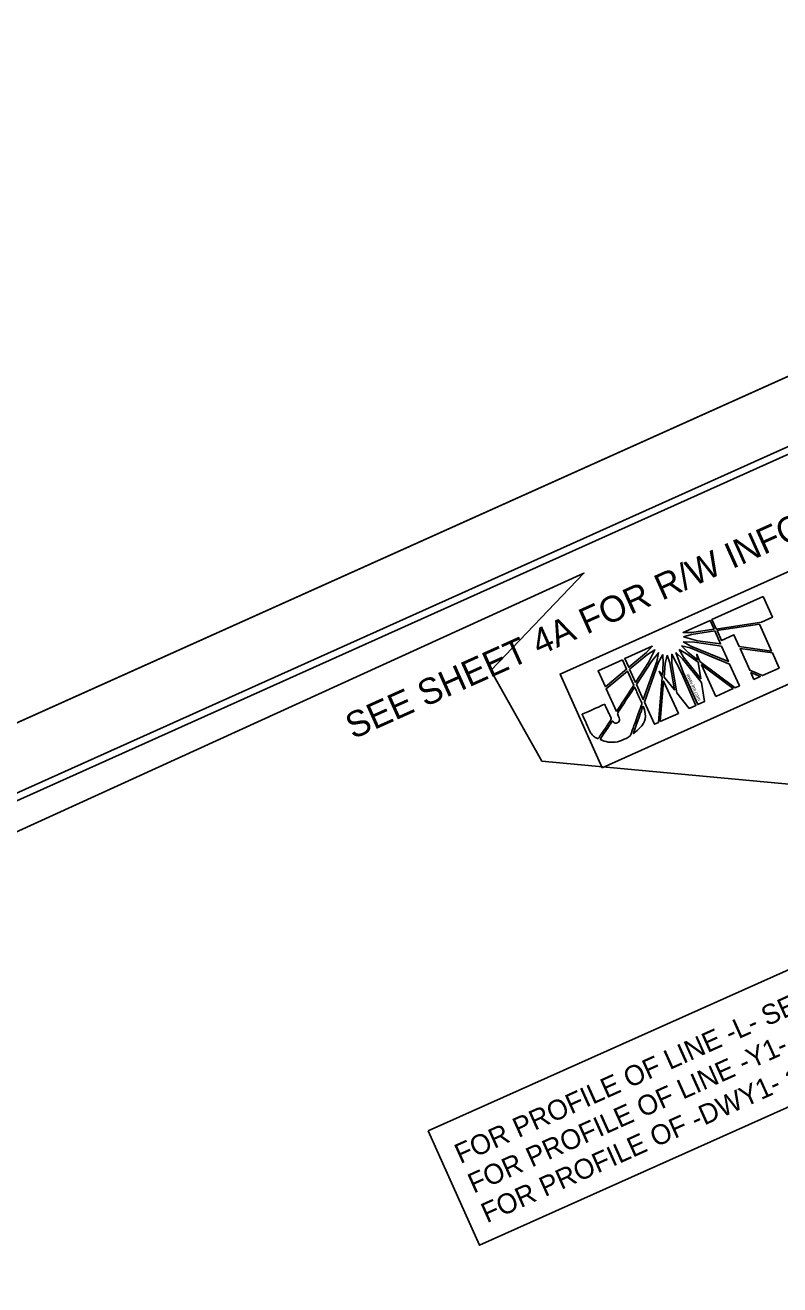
# Model space of a CAD drawing. Extents: x 553939 to 555925, y 502653 to 504347.
# Drawn here: x 554932.1 to 555197.2, y 503904.2 to 504346.6 of the extents above; entities that cross this region are included whole.
import ezdxf

# ---------------------------------------------------------------- set-up
doc = ezdxf.new("R2010")
doc.units = 0
for name, color, linetype in [('Matchline', 7, 'Continuous'), ('Prop Horizontal Alignment Curve and Spiral Data', 7, 'Continuous'), ('Sheet Border Standard 30in CELL', 7, 'Continuous'), ('Sheet Clip Boundary CELL', 7, 'Continuous'), ('Sheet Cutting Line CELL', 7, 'Continuous'), ('Sheet Plot Border Inside CELL', 7, 'Continuous'), ('Sheet Plot Border Outside CELL', 7, 'Continuous')]:
    doc.layers.add(name, color=color, linetype=linetype)

msp = doc.modelspace()

# ---------------------------------------------------------------- linework, layer by layer
at = {"layer": 'Matchline'}
for p, q in [((555191.33, 504145.99), (555173.38, 504137.91)), ((555194.64, 504138.64), (555191.33, 504145.99)), ((555172.74, 504137.57), (555163.26, 504133.36)), ((555174.12, 504134.5), (555172.74, 504137.57)), ((555173.38, 504137.91), (555174.87, 504134.62)), ((555190.82, 504136.92), (555194.64, 504138.64)), ((555163.26, 504133.36), (555166.16, 504133.31)), ((555166.16, 504133.31), (555174.12, 504134.5)), ((555174.41, 504133.86), (555166.2, 504132.58)), ((555176.39, 504129.31), (555174.41, 504133.86)), ((555174.87, 504134.62), (555174.91, 504134.52)), ((555174.91, 504134.52), (555190.82, 504136.92)), ((555190.07, 504136.19), (555175.14, 504134.01)), ((555175.14, 504134.01), (555175.17, 504133.96)), ((555175.17, 504133.96), (555176.71, 504130.52)), ((555194.31, 504126.77), (555190.07, 504136.19)), ((555152.38, 504128.46), (555142.77, 504124.14)), ((555150.42, 504126.27), (555152.38, 504128.46)), ((555162.72, 504128.59), (555165, 504126.33)), ((555165.78, 504127.87), (555162.72, 504128.59)), ((555163.26, 504130.07), (555165.97, 504128.46)), ((555167.3, 504129.91), (555163.26, 504130.07)), ((555166.2, 504132.58), (555163.41, 504131.73)), ((555163.41, 504131.73), (555168.31, 504130.41)), ((555165.97, 504128.46), (555179.2, 504123.08)), ((555176.74, 504128.55), (555167.3, 504129.91)), ((555168.31, 504130.41), (555176.39, 504129.31)), ((555176.71, 504130.52), (555181.09, 504132.49)), ((555179.2, 504123.08), (555176.74, 504128.55)), ((555181.09, 504132.49), (555182.94, 504128.39)), ((555182.94, 504128.39), (555194.31, 504126.77)), ((555142.77, 504124.14), (555144.15, 504121.08)), ((555144.15, 504121.08), (555150.42, 504126.27)), ((555150.72, 504125.61), (555144.45, 504120.42)), ((555153.35, 504127.2), (555150.72, 504125.61)), ((555151.11, 504122.74), (555153.35, 504127.2)), ((555154.65, 504126.2), (555152.14, 504123.08)), ((555154.05, 504123.14), (555154.65, 504126.2)), ((555156.1, 504125.61), (555154.62, 504122.84)), ((555156.29, 504122.41), (555156.1, 504125.61)), ((555157.67, 504125.4), (555156.96, 504122.47)), ((555158.62, 504122.66), (555157.67, 504125.4)), ((555162.65, 504119.09), (555159.25, 504125.66)), ((555159.25, 504125.66), (555159.31, 504122.4)), ((555160.66, 504126.29), (555163.25, 504119.36)), ((555163.02, 504124.07), (555160.66, 504126.29)), ((555161.85, 504127.29), (555163.37, 504124.68)), ((555164.48, 504125.86), (555161.85, 504127.29)), ((555169.68, 504115.8), (555163.02, 504124.07)), ((555163.37, 504124.68), (555169.46, 504117.06)), ((555168.49, 504122.85), (555164.48, 504125.86)), ((555165, 504126.33), (555168.36, 504123.76)), ((555179.6, 504122.2), (555165.78, 504127.87)), ((555168.36, 504123.76), (555168.03, 504125.65)), ((555168.03, 504125.65), (555169.15, 504123.15)), ((555183.26, 504127.69), (555186.69, 504120.05)), ((555194.61, 504126.11), (555183.26, 504127.69)), ((555196.99, 504120.81), (555194.61, 504126.11)), ((555141.91, 504123.69), (555133.37, 504119.85)), ((555133.37, 504119.85), (555135.92, 504114.19)), ((555135.92, 504114.19), (555143.39, 504120.4)), ((555143.67, 504119.78), (555136.21, 504113.54)), ((555143.39, 504120.4), (555141.91, 504123.69)), ((555145.89, 504114.83), (555143.67, 504119.78)), ((555144.45, 504120.42), (555146.53, 504115.8)), ((555146.53, 504115.8), (555151.11, 504122.74)), ((555152.14, 504123.08), (555146.86, 504115.05)), ((555149.26, 504109.73), (555154.05, 504123.14)), ((555154.62, 504122.84), (555149.67, 504108.82)), ((555155.86, 504117.46), (555154.85, 504119.71)), ((555154.85, 504119.71), (555155.97, 504118.35)), ((555155.97, 504118.35), (555156.29, 504122.41)), ((555156.96, 504122.47), (555156.57, 504117.66)), ((555160.24, 504113.14), (555158.62, 504122.66)), ((555159.31, 504122.4), (555161.06, 504112.09)), ((555169.46, 504117.06), (555168.49, 504122.85)), ((555169.15, 504123.15), (555181.54, 504113.85)), ((555180.82, 504113.58), (555169.71, 504121.93)), ((555169.71, 504121.93), (555174.7, 504110.83)), ((555183.05, 504114.53), (555179.6, 504122.2)), ((555186.69, 504120.05), (555191.2, 504118.2)), ((555191.2, 504118.2), (555196.99, 504120.81)), ((555154.56, 504101.71), (555155.86, 504117.46)), ((555156.41, 504116.23), (555155.23, 504102.01)), ((555161.59, 504104.87), (555156.41, 504116.23)), ((555156.57, 504117.66), (555160.24, 504113.14)), ((555167.77, 504107.71), (555162.65, 504119.09)), ((555163.25, 504119.36), (555168.38, 504107.98)), ((555170.74, 504109.05), (555169.68, 504115.8)), ((555190.36, 504117.82), (555187.07, 504119.22)), ((555187.07, 504119.22), (555188.14, 504116.83)), ((555188.14, 504116.83), (555190.36, 504117.82)), ((555136.21, 504113.54), (555139.79, 504105.58)), ((555139.79, 504105.58), (555145.89, 504114.83)), ((555146.86, 504115.05), (555149.26, 504109.73)), ((555161.06, 504112.09), (555165.43, 504106.65)), ((555174.7, 504110.83), (555180.82, 504113.58)), ((555181.54, 504113.85), (555183.05, 504114.53)), ((555149.67, 504108.82), (555153.16, 504101.08)), ((555165.43, 504106.65), (555167.77, 504107.71)), ((555168.38, 504107.98), (555170.74, 504109.05)), ((555155.23, 504102.01), (555161.59, 504104.87)), ((555153.16, 504101.08), (555154.56, 504101.71))]:
    msp.add_line(p, q, dxfattribs=at)
msp.add_lwpolyline([(555134.79, 504085.77), (555317.28, 504167.72), (555302.49, 504200.65), (555120.01, 504118.71)], close=True, dxfattribs=at)
for points in [[(555191.33, 504145.99), (555173.38, 504137.91), (555174.87, 504134.62), (555174.91, 504134.52), (555190.82, 504136.92), (555194.64, 504138.64), (555191.33, 504145.99)], [(555166.16, 504133.31), (555174.12, 504134.5), (555172.74, 504137.57), (555163.26, 504133.36), (555166.16, 504133.31)], [(555163.41, 504131.73), (555168.31, 504130.41), (555176.39, 504129.31), (555174.41, 504133.86), (555166.2, 504132.58), (555163.41, 504131.73)], [(555175.14, 504134.01), (555175.17, 504133.96), (555176.71, 504130.52), (555181.09, 504132.49), (555182.94, 504128.39), (555194.31, 504126.77), (555190.07, 504136.19), (555175.14, 504134.01)], [(555150.42, 504126.27), (555152.38, 504128.46), (555142.77, 504124.14), (555144.15, 504121.08), (555150.42, 504126.27)], [(555162.72, 504128.59), (555165, 504126.33), (555168.36, 504123.76), (555168.03, 504125.65), (555169.15, 504123.15), (555181.54, 504113.85), (555183.05, 504114.53), (555179.6, 504122.2), (555165.78, 504127.87), (555162.72, 504128.59)], [(555163.26, 504130.07), (555165.97, 504128.46), (555179.2, 504123.08), (555176.74, 504128.55), (555167.3, 504129.91), (555163.26, 504130.07)], [(555144.45, 504120.42), (555146.53, 504115.8), (555151.11, 504122.74), (555153.35, 504127.2), (555150.72, 504125.61), (555144.45, 504120.42)], [(555146.86, 504115.05), (555149.26, 504109.73), (555154.05, 504123.14), (555154.65, 504126.2), (555152.14, 504123.08), (555146.86, 504115.05)], [(555156.1, 504125.61), (555154.62, 504122.84), (555149.67, 504108.82), (555153.16, 504101.08), (555154.56, 504101.71), (555155.86, 504117.46), (555154.85, 504119.71), (555155.97, 504118.35), (555156.29, 504122.41), (555156.1, 504125.61)], [(555157.67, 504125.4), (555156.96, 504122.47), (555156.57, 504117.66), (555160.24, 504113.14), (555158.62, 504122.66), (555157.67, 504125.4)], [(555159.31, 504122.4), (555161.06, 504112.09), (555165.43, 504106.65), (555167.77, 504107.71), (555162.65, 504119.09), (555159.25, 504125.66), (555159.31, 504122.4)], [(555160.66, 504126.29), (555163.25, 504119.36), (555168.38, 504107.98), (555170.74, 504109.05), (555169.68, 504115.8), (555163.02, 504124.07), (555160.66, 504126.29)], [(555161.85, 504127.29), (555163.37, 504124.68), (555169.46, 504117.06), (555168.49, 504122.85), (555164.48, 504125.86), (555161.85, 504127.29)], [(555183.26, 504127.69), (555186.69, 504120.05), (555191.2, 504118.2), (555196.99, 504120.81), (555194.61, 504126.11), (555183.26, 504127.69), (555183.26, 504127.69)], [(555135.92, 504114.19), (555143.39, 504120.4), (555141.91, 504123.69), (555133.37, 504119.85), (555135.92, 504114.19)], [(555139.79, 504105.58), (555145.89, 504114.83), (555143.67, 504119.78), (555136.21, 504113.54), (555139.79, 504105.58)], [(555174.7, 504110.83), (555180.82, 504113.58), (555169.71, 504121.93), (555174.7, 504110.83)], [(555155.23, 504102.01), (555161.59, 504104.87), (555156.41, 504116.23), (555155.23, 504102.01)], [(555188.14, 504116.83), (555188.14, 504116.83), (555190.36, 504117.82), (555187.07, 504119.22), (555188.14, 504116.83)]]:
    msp.add_lwpolyline(points, dxfattribs=at)
for points in [[(555140.12, 504101.58), (555139.61, 504101.35), (555139.05, 504101.44), (555138.44, 504102.3), (555138.44, 504102.3), (555134.02, 504095.75), (555134.02, 504095.75), (555136.8, 504094.61), (555140.35, 504094.79), (555142.9, 504095.93), (555143.56, 504096.23), (555144.04, 504096.52), (555144.68, 504096.97), (555144.68, 504096.97), (555148.8, 504108.38), (555148.8, 504108.38), (555148.8, 504108.38), (555146.21, 504114.13), (555146.21, 504114.13), (555146.21, 504114.13), (555140.12, 504104.86), (555140.12, 504104.86), (555141.09, 504102.71), (555140.83, 504101.9), (555140.12, 504101.58)], [(555140.12, 504101.58), (555139.61, 504101.35), (555139.05, 504101.44), (555138.44, 504102.3), (555138.44, 504102.3), (555134.02, 504095.75), (555134.02, 504095.75), (555136.8, 504094.61), (555140.35, 504094.79), (555142.9, 504095.93), (555143.56, 504096.23), (555144.04, 504096.52), (555144.68, 504096.97), (555144.68, 504096.97), (555148.8, 504108.38), (555148.8, 504108.38), (555148.8, 504108.38), (555146.21, 504114.13), (555146.21, 504114.13), (555146.21, 504114.13), (555140.12, 504104.86), (555140.12, 504104.86), (555141.09, 504102.71), (555140.83, 504101.9), (555140.12, 504101.58)], [(555135.69, 504108.14), (555135.69, 504108.14), (555127.79, 504104.58), (555127.79, 504104.58), (555127.79, 504104.58), (555130.02, 504099.64), (555130.02, 504099.64), (555130.02, 504099.64), (555130.25, 504099.12), (555130.25, 504099.12), (555130.95, 504097.57), (555132.01, 504096.57), (555133.37, 504095.95), (555133.37, 504095.95), (555138.09, 504102.82), (555138.05, 504102.91), (555138.05, 504102.91), (555135.69, 504108.14), (555135.69, 504108.14)], [(555149.2, 504107.48), (555149.2, 504107.48), (555145.64, 504097.63), (555145.64, 504097.63), (555148.54, 504099.9), (555150.81, 504103.51), (555149.2, 504107.48)]]:
    msp.add_open_spline(points, degree=3, dxfattribs=at)
at = {"layer": 'Prop Horizontal Alignment Curve and Spiral Data'}
msp.add_lwpolyline([(555073.67, 503958.23), (555091.71, 503918.08), (555365.32, 504040.41), (555347.29, 504080.56), (555073.67, 503958.23)], dxfattribs=at)
at = {"layer": 'Sheet Border Standard 30in CELL'}
msp.add_lwpolyline([(555469.6, 504316.85), (554101.23, 503702.4), (554531.34, 502744.54), (555899.72, 503358.98)], close=True, dxfattribs=at)
at = {"layer": 'Sheet Clip Boundary CELL'}
for points in [[(554122.43, 503695.68), (555128.42, 504154.2), (555095.7, 504120), (555113.65, 504088.12), (555364.03, 504064.84), (555538.05, 504147.98), (555542.54, 504077.37), (555561.42, 504000.98), (555608.35, 503927.62), (555814.87, 503478.7), (555868.57, 503357.36), (555699.98, 503280.3), (555640.99, 503255.83), (555512.69, 503541.56), (555029.44, 503324.56), (555157.75, 503038.83), (555094.66, 503015.3), (554759.27, 502917.8)], [(554122.43, 503695.68), (555128.42, 504154.2), (555095.7, 504120), (555113.65, 504088.12), (555364.03, 504064.84), (555538.05, 504147.98), (555542.54, 504077.37), (555561.42, 504000.98), (555610.11, 503951.13), (555644.95, 503906.87), (555662.42, 503867.97), (555642.54, 503853.07), (555814.87, 503478.7), (555868.57, 503357.36), (555699.98, 503280.3), (555640.99, 503255.83), (555512.69, 503541.56), (555029.44, 503324.56), (555157.75, 503038.83), (555094.66, 503015.3), (554864.55, 502951)]]:
    msp.add_lwpolyline(points, dxfattribs=at)
at = {"layer": 'Sheet Cutting Line CELL'}
msp.add_line((555474.87, 504346.62), (553938.64, 503656.8), dxfattribs=at)
at = {"layer": 'Sheet Plot Border Inside CELL'}
msp.add_lwpolyline([(555479.96, 504324.29), (553959.7, 503641.65), (554391.9, 502679.13), (555912.16, 503361.78)], close=True, dxfattribs=at)
at = {"layer": 'Sheet Plot Border Outside CELL'}
msp.add_lwpolyline([(555474.87, 504346.62), (553938.64, 503656.8), (554389.23, 502653.32), (555925.47, 503343.14)], close=True, dxfattribs=at)

# ---------------------------------------------------------------- texts
at = {"layer": 'Matchline'}
msp.add_text('www.jmt.com', height=1.2413, rotation=294.1816, dxfattribs=at).set_placement((555164.35, 504118.46))
at = {"layer": 'Prop Horizontal Alignment Curve and Spiral Data'}
for s, height, p in [('SEE SHEET 4A FOR R/W INFORMATION', 9.1, (555047.27, 504095.7)), ('FOR PROFILE OF LINE -L- SEE SHEET 10', 7, (555084.98, 503946.56)), ('FOR PROFILE OF -DWY1- and -DWY2- SEE SHEET 14', 7, (555094.3, 503925.8)), ('FOR PROFILE OF LINE -Y1- SEE SHEET 12', 7, (555089.64, 503936.18))]:
    msp.add_text(s, height=height, rotation=24.1816, dxfattribs=at).set_placement(p)

doc.saveas('drawing.dxf')
